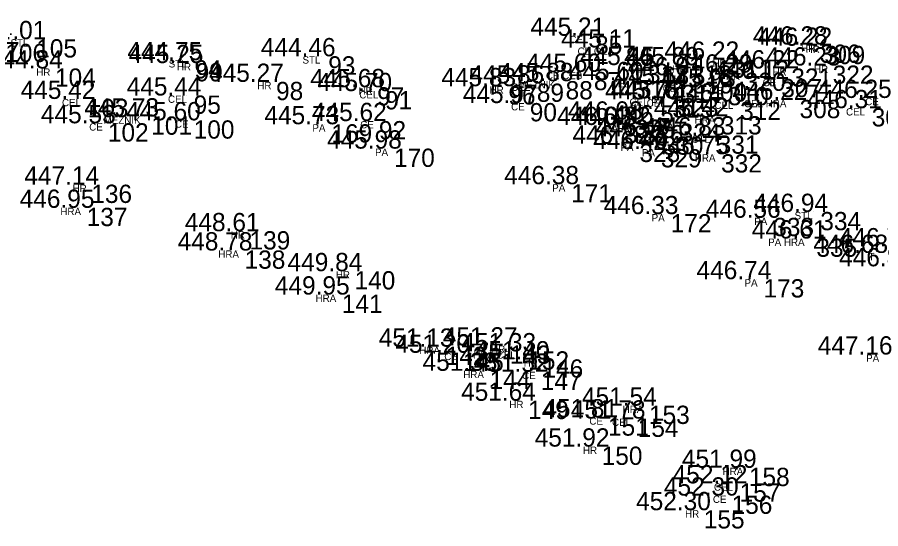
# Model space of a CAD drawing. Extents: x -639390 to -639075, y -1138747 to -1138358.
# Drawn here: x -639263.88 to -639228.45, y -1138663.31 to -1138642.32 of the extents above; entities that cross this region are included whole.
import ezdxf

# ---------------------------------------------------------------- set-up
doc = ezdxf.new("R2010")
doc.units = 0
for name, color, linetype in [('Vrstva 11', 7, 'Continuous'), ('Vrstva 12', 7, 'Continuous'), ('Vrstva 13', 7, 'Continuous'), ('Vrstva 57', 7, 'Continuous')]:
    doc.layers.add(name, color=color, linetype=linetype)

msp = doc.modelspace()

# ---------------------------------------------------------------- linework, layer by layer
at = {"layer": 'Vrstva 11'}
for p, q in [((-639263.38, -1138643.22), (-639263.38, -1138643.22)), ((-639240.45, -1138643.08), (-639240.45, -1138643.08)), ((-639239.19, -1138643.56), (-639239.19, -1138643.56)), ((-639231.23, -1138643.44), (-639231.23, -1138643.44)), ((-639231.04, -1138643.49), (-639231.04, -1138643.49)), ((-639251.4, -1138643.92), (-639251.4, -1138643.92)), ((-639256.89, -1138644.08), (-639256.89, -1138644.08)), ((-639256.84, -1138644.2), (-639256.84, -1138644.2)), ((-639238.32, -1138644.28), (-639238.32, -1138644.28)), ((-639236.51, -1138644.29), (-639236.51, -1138644.29)), ((-639234.86, -1138644.06), (-639234.86, -1138644.06)), ((-639230.7, -1138644.3), (-639230.7, -1138644.3)), ((-639262.61, -1138644.42), (-639262.61, -1138644.42)), ((-639240.5, -1138644.56), (-639240.5, -1138644.56)), ((-639234.31, -1138644.59), (-639234.31, -1138644.59)), ((-639232.4, -1138644.42), (-639232.4, -1138644.42)), ((-639253.54, -1138644.97), (-639253.54, -1138644.97)), ((-639241.66, -1138644.94), (-639241.66, -1138644.94)), ((-639238.75, -1138644.9), (-639238.75, -1138644.9)), ((-639236.46, -1138644.7), (-639236.46, -1138644.7)), ((-639232.81, -1138644.85), (-639232.81, -1138644.85)), ((-639249.39, -1138645.19), (-639249.39, -1138645.19)), ((-639249.07, -1138645.35), (-639249.07, -1138645.35)), ((-639244.01, -1138645.15), (-639244.01, -1138645.15)), ((-639242.84, -1138645.04), (-639242.84, -1138645.04)), ((-639236.91, -1138645.09), (-639236.91, -1138645.09)), ((-639235, -1138645.18), (-639235, -1138645.18)), ((-639261.27, -1138645.67), (-639261.27, -1138645.67)), ((-639256.92, -1138645.53), (-639256.92, -1138645.53)), ((-639237.28, -1138645.69), (-639237.28, -1138645.69)), ((-639237.06, -1138645.65), (-639237.06, -1138645.65)), ((-639232.06, -1138645.71), (-639232.06, -1138645.71)), ((-639228.6, -1138645.63), (-639228.6, -1138645.63)), ((-639243.13, -1138645.84), (-639243.13, -1138645.84)), ((-639234.5, -1138645.78), (-639234.5, -1138645.78)), ((-639229.1, -1138646.05), (-639229.1, -1138646.05)), ((-639258.66, -1138646.39), (-639258.66, -1138646.39)), ((-639235.29, -1138646.38), (-639235.29, -1138646.38)), ((-639260.44, -1138646.67), (-639260.44, -1138646.67)), ((-639256.92, -1138646.55), (-639256.92, -1138646.55)), ((-639251.27, -1138646.71), (-639251.27, -1138646.71)), ((-639249.32, -1138646.58), (-639249.32, -1138646.58)), ((-639239.26, -1138646.74), (-639239.26, -1138646.74)), ((-639238.82, -1138646.52), (-639238.82, -1138646.52)), ((-639238.49, -1138646.74), (-639238.49, -1138646.74)), ((-639236.98, -1138646.68), (-639236.98, -1138646.68)), ((-639237.68, -1138647.21), (-639237.68, -1138647.21)), ((-639235.42, -1138647.17), (-639235.42, -1138647.17)), ((-639248.7, -1138647.71), (-639248.7, -1138647.71)), ((-639238.63, -1138647.51), (-639238.63, -1138647.51)), ((-639237.75, -1138647.73), (-639237.75, -1138647.73)), ((-639235.28, -1138647.94), (-639235.28, -1138647.94)), ((-639261.12, -1138649.19), (-639261.12, -1138649.19)), ((-639241.43, -1138649.17), (-639241.43, -1138649.17)), ((-639261.31, -1138650.14), (-639261.31, -1138650.14)), ((-639231.21, -1138650.31), (-639231.21, -1138650.31)), ((-639237.35, -1138650.4), (-639237.35, -1138650.4)), ((-639233.14, -1138650.55), (-639233.14, -1138650.55)), ((-639254.63, -1138651.1), (-639254.63, -1138651.1)), ((-639231.37, -1138651.4), (-639231.37, -1138651.4)), ((-639254.83, -1138651.89), (-639254.83, -1138651.89)), ((-639228.75, -1138651.99), (-639228.75, -1138651.99)), ((-639250.32, -1138652.74), (-639250.32, -1138652.74)), ((-639233.54, -1138653.07), (-639233.54, -1138653.07)), ((-639250.84, -1138653.7), (-639250.84, -1138653.7)), ((-639246.58, -1138655.84), (-639246.58, -1138655.84)), ((-639243.95, -1138655.79), (-639243.95, -1138655.79)), ((-639245.87, -1138656.09), (-639245.87, -1138656.09)), ((-639243.19, -1138656.03), (-639243.19, -1138656.03)), ((-639228.55, -1138656.16), (-639228.55, -1138656.16)), ((-639242.61, -1138656.36), (-639242.61, -1138656.36)), ((-639244.78, -1138656.83), (-639244.78, -1138656.83)), ((-639242.68, -1138656.87), (-639242.68, -1138656.87)), ((-639243.2, -1138658.06), (-639243.2, -1138658.06)), ((-639238.24, -1138658.26), (-639238.24, -1138658.26)), ((-639239.92, -1138658.74), (-639239.92, -1138658.74)), ((-639238.7, -1138658.79), (-639238.7, -1138658.79)), ((-639240.18, -1138659.94), (-639240.18, -1138659.94)), ((-639234.14, -1138660.81), (-639234.14, -1138660.81)), ((-639234.52, -1138661.45), (-639234.52, -1138661.45)), ((-639234.85, -1138661.95), (-639234.85, -1138661.95)), ((-639235.99, -1138662.55), (-639235.99, -1138662.55))]:
    msp.add_line(p, q, dxfattribs=at)

# ---------------------------------------------------------------- texts
at = {"layer": 'Vrstva 12'}
for s, p in [('444.01 ', (-639265.755, -1138643.22)), ('445.21 ', (-639242.825, -1138643.08)), ('445.11 ', (-639241.565, -1138643.56)), ('446.28 ', (-639233.699, -1138643.44)), ('446.22 ', (-639233.509, -1138643.49)), ('444.46 ', (-639253.886, -1138643.92)), ('444.75 ', (-639259.36, -1138644.08)), ('445.25 ', (-639259.31, -1138644.2)), ('445.45 ', (-639240.79, -1138644.28)), ('445.89 ', (-639238.979, -1138644.29)), ('446.22 ', (-639237.329, -1138644.06)), ('446.23 ', (-639233.169, -1138644.3)), ('444.84 ', (-639265.079, -1138644.42)), ('445.60 ', (-639242.999, -1138644.56)), ('446.01 ', (-639238.835, -1138644.7)), ('446.29 ', (-639236.779, -1138644.59)), ('446.22 ', (-639234.869, -1138644.42)), ('445.27 ', (-639256.009, -1138644.97)), ('445.86 ', (-639245.326, -1138645.04)), ('445.88 ', (-639244.129, -1138644.94)), ('445.60 ', (-639241.249, -1138644.9)), ('446.12 ', (-639235.279, -1138644.85)), ('445.68 ', (-639251.859, -1138645.19)), ('445.70 ', (-639251.569, -1138645.35)), ('445.83 ', (-639246.479, -1138645.15)), ('445.68 ', (-639239.379, -1138645.09)), ('445.93 ', (-639237.469, -1138645.18)), ('445.42 ', (-639263.739, -1138645.67)), ('445.44 ', (-639259.389, -1138645.53)), ('445.76 ', (-639239.766, -1138645.69)), ('445.75 ', (-639239.53, -1138645.65)), ('446.22 ', (-639234.529, -1138645.71)), ('446.25 ', (-639231.07, -1138645.63)), ('445.97 ', (-639245.599, -1138645.84)), ('446.00 ', (-639236.999, -1138645.78)), ('446.31 ', (-639231.475, -1138646.05)), ('445.73 ', (-639261.129, -1138646.39)), ('446.42 ', (-639237.759, -1138646.38)), ('445.53 ', (-639262.909, -1138646.67)), ('445.60 ', (-639259.419, -1138646.55)), ('445.73 ', (-639253.739, -1138646.71)), ('445.62 ', (-639251.789, -1138646.58)), ('446.03 ', (-639241.729, -1138646.74)), ('446.08 ', (-639241.289, -1138646.52)), ('446.32 ', (-639240.959, -1138646.74)), ('446.52 ', (-639239.449, -1138646.68)), ('446.83 ', (-639237.889, -1138647.17)), ('446.28 ', (-639241.099, -1138647.51)), ('446.47 ', (-639240.149, -1138647.21)), ('445.98 ', (-639251.169, -1138647.71)), ('446.40 ', (-639240.249, -1138647.73)), ('446.75 ', (-639237.75, -1138647.94)), ('447.14 ', (-639263.589, -1138649.19)), ('446.38 ', (-639243.899, -1138649.17)), ('446.95 ', (-639263.78, -1138650.14)), ('446.94 ', (-639233.679, -1138650.31)), ('446.33 ', (-639239.819, -1138650.4)), ('446.56 ', (-639235.626, -1138650.55)), ('448.61 ', (-639257.005, -1138651.1)), ('446.61 ', (-639233.745, -1138651.4)), ('446.70 ', (-639230.169, -1138651.72)), ('448.78 ', (-639257.299, -1138651.89)), ('446.68 ', (-639231.219, -1138651.99)), ('449.84 ', (-639252.789, -1138652.74)), ('446.88 ', (-639230.159, -1138652.54)), ('446.74 ', (-639236.009, -1138653.07)), ('449.95 ', (-639253.31, -1138653.7)), ('451.13 ', (-639249.049, -1138655.84)), ('451.27 ', (-639246.419, -1138655.79)), ('451.33 ', (-639245.659, -1138656.03)), ('451.20 ', (-639248.369, -1138656.09)), ('451.40 ', (-639245.109, -1138656.36)), ('447.16 ', (-639231.036, -1138656.16)), ('451.38 ', (-639247.249, -1138656.83)), ('451.52 ', (-639245.149, -1138656.87)), ('451.64 ', (-639245.669, -1138658.06)), ('451.54 ', (-639240.709, -1138658.26)), ('451.81 ', (-639242.295, -1138658.74)), ('451.78 ', (-639241.169, -1138658.79)), ('451.92 ', (-639242.649, -1138659.94)), ('451.99 ', (-639236.609, -1138660.81)), ('452.12 ', (-639236.989, -1138661.45)), ('452.30 ', (-639237.349, -1138661.95)), ('452.30 ', (-639238.489, -1138662.55))]:
    msp.add_text(s, height=0.75, dxfattribs=at).set_placement(p)
at = {"layer": 'Vrstva 13'}
for s, p in [(' 105', (-639263.38, -1138643.97)), (' 85', (-639240.45, -1138643.83)), (' 107', (-639265.74, -1138644.08)), (' 106', (-639264.65, -1138644.16)), (' 86', (-639239.19, -1138644.31)), (' 306', (-639231.23, -1138644.19)), (' 309', (-639231.04, -1138644.24)), (' 93', (-639251.4, -1138644.67)), (' 94', (-639256.89, -1138644.83)), (' 99', (-639256.84, -1138644.95)), (' 317', (-639238.32, -1138645.03)), (' 318', (-639236.51, -1138645.04)), (' 311', (-639234.86, -1138644.81)), (' 322', (-639230.7, -1138645.05)), (' 104', (-639262.61, -1138645.17)), (' 87', (-639240.5, -1138645.31)), (' 320', (-639234.31, -1138645.34)), (' 321', (-639232.4, -1138645.17)), (' 98', (-639253.54, -1138645.72)), (' 88', (-639241.66, -1138645.69)), (' 316', (-639238.75, -1138645.65)), (' 319', (-639236.46, -1138645.45)), (' 307', (-639232.81, -1138645.6)), (' 97', (-639249.39, -1138645.94)), (' 91', (-639249.07, -1138646.1)), (' 96', (-639244.01, -1138645.9)), (' 89', (-639242.84, -1138645.79)), (' 314', (-639236.91, -1138645.84)), (' 310', (-639235, -1138645.93)), (' 103', (-639261.27, -1138646.42)), (' 95', (-639256.92, -1138646.28)), (' 315', (-639237.28, -1138646.44)), (' 323', (-639237.06, -1138646.4)), (' 308', (-639232.06, -1138646.46)), (' 90', (-639243.13, -1138646.59)), (' 312', (-639234.5, -1138646.53)), (' 305', (-639229.1, -1138646.8)), (' 101', (-639258.66, -1138647.14)), (' 313', (-639235.29, -1138647.13)), (' 102', (-639260.44, -1138647.42)), (' 100', (-639256.92, -1138647.3)), (' 169', (-639251.27, -1138647.46)), (' 92', (-639249.32, -1138647.33)), (' 327', (-639239.26, -1138647.49)), (' 325', (-639238.82, -1138647.27)), (' 326', (-639238.49, -1138647.49)), (' 324', (-639236.98, -1138647.43)), (' 330', (-639237.68, -1138647.96)), (' 331', (-639235.42, -1138647.92)), (' 170', (-639248.7, -1138648.46)), (' 328', (-639238.63, -1138648.26)), (' 329', (-639237.75, -1138648.48)), (' 332', (-639235.28, -1138648.69)), (' 136', (-639261.12, -1138649.94)), (' 171', (-639241.43, -1138649.92)), (' 137', (-639261.31, -1138650.89)), (' 334', (-639231.21, -1138651.06)), (' 172', (-639237.35, -1138651.15)), (' 333', (-639233.14, -1138651.3)), (' 139', (-639254.63, -1138651.85)), (' 335', (-639231.37, -1138652.15)), (' 138', (-639254.83, -1138652.64)), (' 140', (-639250.32, -1138653.49)), (' 173', (-639233.54, -1138653.82)), (' 141', (-639250.84, -1138654.45)), (' 142', (-639246.58, -1138656.59)), (' 143', (-639243.95, -1138656.54)), (' 145', (-639245.87, -1138656.84)), (' 152', (-639243.19, -1138656.78)), (' 146', (-639242.61, -1138657.11)), (' 144', (-639244.78, -1138657.58)), (' 147', (-639242.68, -1138657.62)), (' 149', (-639243.2, -1138658.81)), (' 153', (-639238.24, -1138659.01)), (' 151', (-639239.92, -1138659.49)), (' 154', (-639238.7, -1138659.54)), (' 150', (-639240.18, -1138660.69)), (' 158', (-639234.14, -1138661.56)), (' 157', (-639234.52, -1138662.2)), (' 156', (-639234.85, -1138662.7)), (' 155', (-639235.99, -1138663.3))]:
    msp.add_text(s, height=0.75, dxfattribs=at).set_placement(p)
at = {"layer": 'Vrstva 57'}
for s, p in [('STL', (-639264.155, -1138643.52)), ('CEL', (-639241.225, -1138643.38)), ('CE CEA', (-639240.89, -1138643.86)), ('HR', (-639231.719, -1138643.74)), ('HR', (-639231.529, -1138643.79)), ('STL', (-639252.175, -1138644.22)), ('STL', (-639257.665, -1138644.38)), ('HR', (-639257.329, -1138644.5)), ('CE', (-639238.807, -1138644.58)), ('HR', (-639236.999, -1138644.59)), ('HR', (-639235.349, -1138644.36)), ('HR', (-639231.189, -1138644.6)), ('HR', (-639263.099, -1138644.72)), ('CE CEB', (-639242.189, -1138644.86)), ('HR', (-639234.799, -1138644.89)), ('HR', (-639232.889, -1138644.72)), ('HR', (-639254.029, -1138645.27)), ('MEZNIK', (-639243.335, -1138645.24)), ('CEL', (-639239.525, -1138645.2)), ('HR', (-639236.949, -1138645)), ('CE', (-639233.297, -1138645.15)), ('HR', (-639249.879, -1138645.49)), ('CEL', (-639249.845, -1138645.65)), ('HR', (-639244.499, -1138645.45)), ('CEL', (-639243.615, -1138645.34)), ('CE', (-639237.397, -1138645.39)), ('CE', (-639235.488, -1138645.48)), ('CEL', (-639262.045, -1138645.97)), ('CEL', (-639257.695, -1138645.83)), ('CEL PA', (-639238.76, -1138645.95)), ('CEL', (-639238.055, -1138645.99)), ('CEL HRA', (-639234.06, -1138646.01)), ('CE', (-639229.088, -1138645.93)), ('CE', (-639243.618, -1138646.14)), ('CEL', (-639235.275, -1138646.08)), ('CEL', (-639229.875, -1138646.35)), ('MEZNIK', (-639260.335, -1138646.69)), ('HRA', (-639236.09, -1138646.68)), ('CE', (-639260.927, -1138646.97)), ('CE', (-639257.407, -1138646.85)), ('PA', (-639251.77, -1138647.01)), ('CE', (-639249.807, -1138646.88)), ('PA', (-639239.76, -1138647.04)), ('PA', (-639239.32, -1138646.82)), ('HRA', (-639239.29, -1138647.04)), ('HRA', (-639237.78, -1138646.98)), ('HRA', (-639238.48, -1138647.51)), ('STL', (-639236.195, -1138647.47)), ('PA', (-639249.2, -1138648.01)), ('PA', (-639239.13, -1138647.81)), ('PA', (-639238.25, -1138648.03)), ('HRA', (-639236.08, -1138648.24)), ('HR', (-639261.609, -1138649.49)), ('PA', (-639241.93, -1138649.47)), ('HRA', (-639262.11, -1138650.44)), ('STL', (-639231.985, -1138650.61)), ('PA', (-639237.85, -1138650.7)), ('PA', (-639233.64, -1138650.85)), ('HR', (-639255.119, -1138651.4)), ('PA HRA', (-639233.07, -1138651.7)), ('HRA', (-639255.63, -1138652.19)), ('T', (-639228.95, -1138652.29)), ('HR', (-639250.809, -1138653.04)), ('PA', (-639234.04, -1138653.37)), ('HRA', (-639251.64, -1138654)), ('HRA', (-639247.38, -1138656.14)), ('HR', (-639244.439, -1138656.09)), ('CE', (-639246.358, -1138656.39)), ('HRA CEL', (-639245.165, -1138656.33)), ('PA', (-639229.05, -1138656.46)), ('HR', (-639243.099, -1138656.66)), ('HRA', (-639245.58, -1138657.13)), ('CE', (-639243.167, -1138657.17)), ('HR', (-639243.689, -1138658.36)), ('HRA', (-639239.04, -1138658.56)), ('CE', (-639240.407, -1138659.04)), ('CEL', (-639239.475, -1138659.09)), ('HR', (-639240.669, -1138660.24)), ('HRA', (-639234.94, -1138661.11)), ('CEL', (-639235.295, -1138661.75)), ('CE', (-639235.338, -1138662.25)), ('HR', (-639236.479, -1138662.85))]:
    msp.add_text(s, height=0.3, dxfattribs=at).set_placement(p)

doc.saveas('drawing.dxf')
